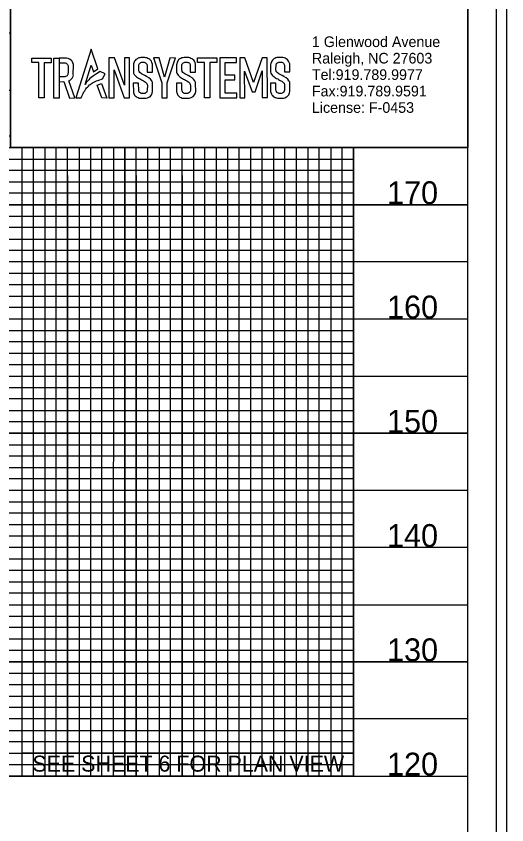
# Model space of a CAD drawing. Extents: x 1779926 to 1781610, y 620464 to 621564.
# Drawn here: x 1781395.5 to 1781610, y 621017.9 to 621371.7 of the extents above; entities that cross this region are included whole.
import ezdxf

# ---------------------------------------------------------------- set-up
doc = ezdxf.new("R2010")
doc.units = 0
for name, color, linetype in [('Exist Vertical Profile Vertical Axis Label', 7, 'Continuous'), ('Old_Level_2', 7, 'Continuous'), ('Old_Level_58', 7, 'Continuous'), ('Prop DSN Text', 7, 'Continuous'), ('Prop Grid Mask', 7, 'Continuous'), ('Scratch_Level_0', 7, 'Continuous'), ('Sheet DOT Grid CELL', 7, 'Continuous'), ('Sheet Layout Profile Border Port 1', 7, 'Continuous'), ('Sheet Plot Border Inside CELL', 7, 'Continuous'), ('Sheet Plot Border Outside CELL', 7, 'Continuous'), ('Sheet Profile CELL', 7, 'Continuous'), ('Sheet Profile Grid Major CELL', 7, 'Continuous'), ('Sheet Profile Grid Middle CELL', 7, 'Continuous'), ('Sheet Profile Grid Minor CELL', 7, 'Continuous')]:
    doc.layers.add(name, color=color, linetype=linetype)

msp = doc.modelspace()

# ---------------------------------------------------------------- linework, layer by layer
at = {"layer": 'Old_Level_58'}
msp.add_lwpolyline([(1781392.96, 621378.14), (1781592.95, 621378.14), (1781592.95, 621314.19), (1781392.96, 621314.19)], close=True, dxfattribs=at)
at = {"layer": 'Prop Grid Mask'}
msp.add_lwpolyline([(1781542.96, 621049.19), (1781397.96, 621049.19), (1781397.96, 621039.19), (1781542.96, 621039.19)], close=True, dxfattribs=at)
at = {"layer": 'Scratch_Level_0'}
msp.add_lwpolyline([(1780142.96, 621039.19), (1780142.96, 621539.19), (1781392.96, 621539.19), (1781392.96, 621314.19), (1781542.96, 621314.19), (1781542.96, 621039.19)], close=True, dxfattribs=at)
at = {"layer": 'Sheet DOT Grid CELL'}
for p, q in [((1781442.96, 621039.19), (1781442.96, 621314.19)), ((1781492.96, 621039.19), (1781492.96, 621314.19)), ((1781542.96, 621039.19), (1781542.96, 621314.19)), ((1781592.96, 621289.19), (1780092.96, 621289.19)), ((1781592.96, 621239.19), (1780092.96, 621239.19)), ((1781592.96, 621189.19), (1780092.96, 621189.19)), ((1781592.96, 621139.19), (1780092.96, 621139.19)), ((1781592.96, 621089.19), (1780092.96, 621089.19))]:
    msp.add_line(p, q, dxfattribs=at)
at = {"layer": 'Sheet Layout Profile Border Port 1'}
msp.add_lwpolyline([(1780142.96, 621378.14), (1780142.96, 621039.19), (1781542.96, 621039.19), (1781542.96, 621314.19)], dxfattribs=at)
for points in [[(1781428.25, 621357.23), (1781421.58, 621335.89), (1781423.81, 621335.9), (1781424.15, 621336.74), (1781424.72, 621337.9), (1781425.03, 621338.53), (1781425.41, 621339.07), (1781425.93, 621339.83), (1781426.26, 621340.3), (1781426.64, 621340.69), (1781427.02, 621341.08), (1781427.51, 621341.58), (1781427.92, 621341.85), (1781428.33, 621342.18), (1781428.89, 621342.5), (1781429.38, 621342.78), (1781430.6, 621343.35), (1781431.6, 621343.76), (1781433.24, 621344.32), (1781434.38, 621346.46), (1781432.2, 621347.42), (1781430.57, 621346.53), (1781429.19, 621345.63), (1781428.21, 621344.83), (1781427.69, 621344.41), (1781427.15, 621343.84), (1781426.62, 621343.27), (1781426.22, 621342.85), (1781425.84, 621342.2), (1781425.63, 621341.84), (1781428.26, 621350.22), (1781429.26, 621347.33), (1781431.16, 621348.58)], [(1781402.29, 621353.38), (1781410.75, 621353.39), (1781410.75, 621351.31), (1781407.64, 621351.31), (1781407.66, 621335.89), (1781405.31, 621335.89), (1781405.29, 621351.41), (1781402.32, 621351.41)], [(1781411.91, 621353.37), (1781414.22, 621353.38), (1781414.24, 621335.81), (1781411.92, 621335.81)], [(1781414.22, 621351.29), (1781416.61, 621351.29), (1781416.91, 621351.24), (1781417.32, 621351.08), (1781417.64, 621350.86), (1781417.87, 621350.59), (1781418.03, 621350.26), (1781418.15, 621350), (1781418.15, 621349.42), (1781418.16, 621346.93), (1781418.1, 621346.6), (1781418.01, 621346.16), (1781417.88, 621345.86), (1781417.68, 621345.6), (1781417.41, 621345.39), (1781416.99, 621345.24), (1781416.66, 621345.2), (1781416.34, 621345.15), (1781414.23, 621345.14), (1781414.24, 621343.03), (1781416.35, 621343.05), (1781418.72, 621335.88), (1781421.13, 621335.91), (1781418.48, 621343.45), (1781418.86, 621343.58), (1781419.4, 621343.98), (1781419.89, 621344.52), (1781420.23, 621345.15), (1781420.45, 621345.78), (1781420.43, 621345.97), (1781420.48, 621350.53), (1781420.27, 621351.28), (1781419.91, 621351.96), (1781419.5, 621352.43), (1781418.8, 621352.9), (1781418.12, 621353.13), (1781417.45, 621353.35), (1781417.04, 621353.35), (1781414.22, 621353.38)], [(1781436.02, 621353.41), (1781436.03, 621335.95), (1781438.27, 621335.95), (1781438.26, 621348.23), (1781442.71, 621335.93), (1781444.96, 621335.96), (1781444.94, 621353.46), (1781442.76, 621353.46), (1781442.78, 621341.48), (1781438.37, 621353.42)], [(1781452.72, 621347.24), (1781455.03, 621347.24), (1781455.02, 621350.72), (1781454.83, 621351.42), (1781454.55, 621352.01), (1781454.25, 621352.4), (1781453.88, 621352.76), (1781453.44, 621353.04), (1781453.01, 621353.21), (1781453.01, 621353.21), (1781452.55, 621353.41), (1781452.07, 621353.53), (1781451.75, 621353.61), (1781450, 621353.57), (1781449.47, 621353.48), (1781449.02, 621353.4), (1781448.55, 621353.16), (1781448.15, 621352.95), (1781447.76, 621352.67), (1781447.45, 621352.35), (1781447.2, 621351.99), (1781447.01, 621351.59), (1781446.75, 621350.9), (1781446.7, 621350.38), (1781446.7, 621347.21), (1781446.82, 621346.74), (1781447.05, 621346.24), (1781447.34, 621345.83), (1781447.63, 621345.52), (1781448.08, 621345.17), (1781448.54, 621344.83), (1781448.82, 621344.61), (1781449.3, 621344.38), (1781449.79, 621344.16), (1781450.18, 621343.9), (1781450.62, 621343.62), (1781451.15, 621343.35), (1781451.58, 621343.13), (1781452.01, 621342.82), (1781452.32, 621342.52), (1781452.57, 621342.28), (1781452.72, 621341.8), (1781452.82, 621341.5), (1781452.78, 621339.27), (1781452.62, 621338.78), (1781452.38, 621338.36), (1781452.05, 621338.07), (1781451.69, 621337.91), (1781451.35, 621337.84), (1781450.39, 621337.82), (1781450.07, 621337.91), (1781449.74, 621338.1), (1781449.41, 621338.3), (1781449.27, 621338.63), (1781449.13, 621338.97), (1781449.01, 621339.23), (1781448.98, 621342.35), (1781446.64, 621342.32), (1781446.68, 621338.61), (1781446.8, 621338.33), (1781447.07, 621337.46), (1781447.24, 621337.17), (1781447.5, 621336.85), (1781447.88, 621336.48), (1781448.18, 621336.29), (1781448.62, 621336.1), (1781448.78, 621336.04), (1781449.2, 621335.86), (1781449.74, 621335.8), (1781450.13, 621335.76), (1781452.27, 621335.82), (1781452.87, 621335.96), (1781453.69, 621336.33), (1781453.97, 621336.46), (1781454.6, 621337.25), (1781454.93, 621338.04), (1781455.08, 621338.75), (1781455.03, 621342.17), (1781455.02, 621342.64), (1781454.89, 621343.02), (1781454.7, 621343.37), (1781454.16, 621344.13), (1781453.45, 621344.69), (1781452.48, 621345.27), (1781451.73, 621345.71), (1781450.27, 621346.48), (1781449.52, 621347.04), (1781449.19, 621347.46), (1781449.11, 621347.74), (1781449.03, 621348.03), (1781449.08, 621350.46), (1781449.2, 621350.71), (1781449.33, 621350.97), (1781449.51, 621351.12), (1781449.74, 621351.32), (1781450, 621351.42), (1781450.25, 621351.53), (1781450.4, 621351.5), (1781450.42, 621351.58), (1781451.38, 621351.56), (1781451.65, 621351.45), (1781451.93, 621351.34), (1781452.21, 621351.23), (1781452.34, 621351.04), (1781452.52, 621350.76), (1781452.61, 621350.48), (1781452.71, 621350.21), (1781452.7, 621349.9)], [(1781457.99, 621353.42), (1781455.45, 621353.42), (1781459.07, 621342.54), (1781459.1, 621335.99), (1781461.49, 621336.01), (1781461.46, 621342.5), (1781465.12, 621353.46), (1781462.62, 621353.39), (1781460.31, 621345.05)], [(1781471.59, 621347.26), (1781473.9, 621347.26), (1781473.89, 621350.74), (1781473.7, 621351.44), (1781473.42, 621352.03), (1781473.12, 621352.42), (1781472.75, 621352.77), (1781472.31, 621353.06), (1781471.88, 621353.23), (1781471.88, 621353.23), (1781471.43, 621353.42), (1781470.94, 621353.55), (1781470.62, 621353.63), (1781468.87, 621353.59), (1781468.34, 621353.5), (1781467.89, 621353.42), (1781467.43, 621353.18), (1781467.02, 621352.97), (1781466.63, 621352.68), (1781466.32, 621352.37), (1781466.08, 621352.01), (1781465.88, 621351.61), (1781465.63, 621350.91), (1781465.58, 621350.4), (1781465.58, 621347.23), (1781465.69, 621346.75), (1781465.92, 621346.26), (1781466.21, 621345.85), (1781466.51, 621345.54), (1781466.96, 621345.19), (1781467.41, 621344.84), (1781467.69, 621344.62), (1781468.18, 621344.4), (1781468.66, 621344.17), (1781469.05, 621343.92), (1781469.49, 621343.63), (1781470.02, 621343.37), (1781470.45, 621343.15), (1781470.88, 621342.83), (1781471.19, 621342.54), (1781471.44, 621342.3), (1781471.59, 621341.82), (1781471.69, 621341.52), (1781471.65, 621339.28), (1781471.49, 621338.8), (1781471.25, 621338.38), (1781470.92, 621338.09), (1781470.56, 621337.93), (1781470.22, 621337.86), (1781469.26, 621337.84), (1781468.94, 621337.93), (1781468.61, 621338.12), (1781468.28, 621338.31), (1781468.14, 621338.65), (1781468, 621338.98), (1781467.88, 621339.25), (1781467.85, 621342.36), (1781465.51, 621342.34), (1781465.55, 621338.63), (1781465.67, 621338.34), (1781465.94, 621337.48), (1781466.12, 621337.19), (1781466.37, 621336.87), (1781466.75, 621336.5), (1781467.05, 621336.3), (1781467.49, 621336.12), (1781467.65, 621336.05), (1781468.08, 621335.87), (1781468.61, 621335.82), (1781469, 621335.78), (1781471.15, 621335.84), (1781471.74, 621335.98), (1781472.57, 621336.35), (1781472.85, 621336.48), (1781473.47, 621337.27), (1781473.8, 621338.05), (1781473.96, 621338.76), (1781473.9, 621342.19), (1781473.9, 621342.66), (1781473.76, 621343.03), (1781473.57, 621343.39), (1781473.03, 621344.15), (1781472.33, 621344.7), (1781471.35, 621345.28), (1781470.61, 621345.73), (1781469.14, 621346.49), (1781468.39, 621347.06), (1781468.06, 621347.48), (1781467.98, 621347.76), (1781467.91, 621348.05), (1781467.95, 621350.48), (1781468.08, 621350.73), (1781468.2, 621350.99), (1781468.38, 621351.14), (1781468.61, 621351.33), (1781468.87, 621351.44), (1781469.13, 621351.55), (1781469.27, 621351.52), (1781469.29, 621351.59), (1781470.25, 621351.58), (1781470.52, 621351.47), (1781470.8, 621351.36), (1781471.08, 621351.25), (1781471.21, 621351.06), (1781471.39, 621350.78), (1781471.49, 621350.5), (1781471.58, 621350.23), (1781471.57, 621349.92)], [(1781474.74, 621353.45), (1781483.21, 621353.45), (1781483.21, 621351.38), (1781480.1, 621351.38), (1781480.12, 621335.96), (1781477.77, 621335.95), (1781477.75, 621351.48), (1781474.78, 621351.48)], [(1781491.82, 621353.45), (1781484.43, 621353.45), (1781484.45, 621336.02), (1781491.92, 621336.03), (1781491.92, 621338), (1781486.87, 621337.99), (1781486.87, 621343.84), (1781491.08, 621343.84), (1781491.08, 621345.91), (1781486.83, 621345.91), (1781486.83, 621351.41), (1781491.84, 621351.41)], [(1781499.19, 621342.6), (1781495.38, 621353.53), (1781493.17, 621353.42), (1781493.25, 621335.96), (1781495.36, 621335.97), (1781495.31, 621347.65), (1781498.57, 621338.66), (1781499.92, 621338.63), (1781502.99, 621347.76), (1781503.03, 621336.04), (1781505.32, 621336.05), (1781505.25, 621353.47), (1781502.95, 621353.46)], [(1781512.72, 621347.3), (1781515.03, 621347.3), (1781515.03, 621350.77), (1781514.83, 621351.48), (1781514.55, 621352.07), (1781514.25, 621352.46), (1781513.88, 621352.81), (1781513.44, 621353.09), (1781513.02, 621353.27), (1781513.02, 621353.27), (1781512.56, 621353.46), (1781512.08, 621353.58), (1781511.76, 621353.66), (1781510.01, 621353.63), (1781509.48, 621353.54), (1781509.02, 621353.46), (1781508.56, 621353.22), (1781508.15, 621353.01), (1781507.76, 621352.72), (1781507.45, 621352.41), (1781507.21, 621352.04), (1781507.01, 621351.65), (1781506.76, 621350.95), (1781506.71, 621350.44), (1781506.71, 621347.27), (1781506.82, 621346.79), (1781507.05, 621346.3), (1781507.34, 621345.89), (1781507.64, 621345.58), (1781508.09, 621345.23), (1781508.54, 621344.88), (1781508.83, 621344.66), (1781509.31, 621344.44), (1781509.79, 621344.21), (1781510.18, 621343.96), (1781510.62, 621343.67), (1781511.15, 621343.41), (1781511.58, 621343.19), (1781512.01, 621342.87), (1781512.32, 621342.58), (1781512.57, 621342.34), (1781512.73, 621341.86), (1781512.82, 621341.56), (1781512.79, 621339.32), (1781512.62, 621338.84), (1781512.38, 621338.42), (1781512.05, 621338.13), (1781511.7, 621337.97), (1781511.36, 621337.9), (1781510.39, 621337.88), (1781510.07, 621337.97), (1781509.74, 621338.16), (1781509.41, 621338.35), (1781509.27, 621338.69), (1781509.13, 621339.02), (1781509.02, 621339.29), (1781508.98, 621342.4), (1781506.64, 621342.37), (1781506.69, 621338.66), (1781506.8, 621338.38), (1781507.07, 621337.52), (1781507.25, 621337.23), (1781507.5, 621336.91), (1781507.88, 621336.53), (1781508.19, 621336.34), (1781508.62, 621336.16), (1781508.78, 621336.09), (1781509.21, 621335.91), (1781509.74, 621335.86), (1781510.14, 621335.82), (1781512.28, 621335.87), (1781512.87, 621336.01), (1781513.7, 621336.39), (1781513.98, 621336.51), (1781514.6, 621337.31), (1781514.93, 621338.09), (1781515.09, 621338.8), (1781515.04, 621342.22), (1781515.03, 621342.7), (1781514.9, 621343.07), (1781514.71, 621343.43), (1781514.17, 621344.19), (1781513.46, 621344.74), (1781512.48, 621345.32), (1781511.74, 621345.77), (1781510.28, 621346.53), (1781509.52, 621347.09), (1781509.19, 621347.52), (1781509.12, 621347.8), (1781509.04, 621348.08), (1781509.08, 621350.51), (1781509.21, 621350.77), (1781509.33, 621351.02), (1781509.51, 621351.18), (1781509.74, 621351.37), (1781510, 621351.48), (1781510.26, 621351.59), (1781510.41, 621351.56), (1781510.42, 621351.63), (1781511.38, 621351.62), (1781511.66, 621351.51), (1781511.93, 621351.4), (1781512.21, 621351.29), (1781512.34, 621351.09), (1781512.53, 621350.82), (1781512.62, 621350.54), (1781512.71, 621350.26), (1781512.7, 621349.96)], [(1781430.86, 621341.52), (1781432.78, 621342.29), (1781435.04, 621335.85), (1781432.94, 621335.93)]]:
    msp.add_lwpolyline(points, close=True, dxfattribs=at)
at = {"layer": 'Sheet Plot Border Inside CELL'}
msp.add_lwpolyline([(1779938.96, 620486.64), (1781605.46, 620486.64), (1781605.46, 621541.74), (1779938.96, 621541.74)], close=True, dxfattribs=at)
at = {"layer": 'Sheet Plot Border Outside CELL'}
msp.add_lwpolyline([(1779925.96, 620464.19), (1781609.96, 620464.19), (1781609.96, 621564.19), (1779925.96, 621564.19)], close=True, dxfattribs=at)
at = {"layer": 'Sheet Profile CELL'}
msp.add_line((1780092.96, 621039.19), (1781592.96, 621039.19), dxfattribs=at)
msp.add_lwpolyline([(1781592.96, 621539.19), (1780092.96, 621539.19), (1780092.96, 620489.19), (1781592.96, 620489.19)], close=True, dxfattribs=at)
at = {"layer": 'Sheet Profile Grid Major CELL'}
for points in [[(1781542.96, 621314.19), (1781542.96, 621039.19), (1781592.96, 621039.19), (1781592.96, 621389.19)], [(1781392.91, 621339.19), (1780092.96, 621339.19), (1780092.96, 621289.19), (1781592.96, 621289.19)], [(1781442.96, 621314.19), (1781442.96, 621039.19), (1781492.96, 621039.19), (1781492.96, 621039.19), (1781492.96, 621314.19)], [(1781592.96, 621239.19), (1780092.96, 621239.19), (1780092.96, 621189.19), (1781592.96, 621189.19)], [(1781592.96, 621139.19), (1780092.96, 621139.19), (1780092.96, 621139.19), (1780092.96, 621089.19), (1781592.96, 621089.19)]]:
    msp.add_lwpolyline(points, dxfattribs=at)
at = {"layer": 'Sheet Profile Grid Middle CELL'}
for points in [[(1781167.96, 621039.19), (1781217.96, 621039.19), (1781217.96, 621539.19), (1781267.96, 621539.19), (1781267.96, 621039.19), (1781317.96, 621039.19), (1781317.96, 621539.19), (1781367.96, 621539.19), (1781367.96, 621039.19), (1781417.96, 621039.19), (1781417.96, 621314.19)], [(1781392.91, 621364.19), (1780092.96, 621364.19), (1780092.96, 621314.19), (1781417.96, 621314.19)], [(1781417.96, 621314.19), (1781592.96, 621314.19)], [(1781417.96, 621301.99), (1781417.96, 621039.19), (1781467.96, 621039.19), (1781467.96, 621314.19)], [(1781467.96, 621301.99), (1781467.96, 621039.19), (1781517.96, 621039.19), (1781517.96, 621314.19)], [(1781592.96, 621264.19), (1780092.96, 621264.19), (1780092.96, 621214.19), (1781592.96, 621214.19)], [(1781592.96, 621164.19), (1780092.96, 621164.19), (1780092.96, 621114.19), (1781592.96, 621114.19)], [(1781592.96, 621064.19), (1780092.96, 621064.19)]]:
    msp.add_lwpolyline(points, dxfattribs=at)
at = {"layer": 'Sheet Profile Grid Minor CELL'}
for p, q in [((1781542.96, 621304.19), (1780142.96, 621304.19)), ((1780142.96, 621299.19), (1781542.96, 621299.19)), ((1781542.96, 621294.19), (1780142.96, 621294.19)), ((1780142.96, 621284.19), (1781542.96, 621284.19)), ((1781542.96, 621279.19), (1780142.96, 621279.19)), ((1780142.96, 621274.19), (1781542.96, 621274.19)), ((1781542.96, 621269.19), (1780142.96, 621269.19)), ((1780142.96, 621259.19), (1781542.96, 621259.19)), ((1781542.96, 621254.19), (1780142.96, 621254.19)), ((1780142.96, 621249.19), (1781542.96, 621249.19)), ((1781542.96, 621244.19), (1780142.96, 621244.19)), ((1780142.96, 621234.19), (1781542.96, 621234.19)), ((1781542.96, 621229.19), (1780142.96, 621229.19)), ((1780142.96, 621224.19), (1781542.96, 621224.19)), ((1781542.96, 621219.19), (1780142.96, 621219.19)), ((1780142.96, 621209.19), (1781542.96, 621209.19)), ((1781542.96, 621204.19), (1780142.96, 621204.19)), ((1780142.96, 621199.19), (1781542.96, 621199.19)), ((1781542.96, 621194.19), (1780142.96, 621194.19)), ((1780142.96, 621184.19), (1781542.96, 621184.19)), ((1781542.96, 621179.19), (1780142.96, 621179.19)), ((1780142.96, 621174.19), (1781542.96, 621174.19)), ((1781542.96, 621169.19), (1780142.96, 621169.19)), ((1780142.96, 621159.19), (1781542.96, 621159.19)), ((1781542.96, 621154.19), (1780142.96, 621154.19)), ((1781542.96, 621149.19), (1780142.96, 621149.19)), ((1781542.96, 621144.19), (1780142.96, 621144.19)), ((1780142.96, 621134.19), (1781542.96, 621134.19)), ((1781542.96, 621129.19), (1780142.96, 621129.19)), ((1780142.96, 621124.19), (1781542.96, 621124.19)), ((1781542.96, 621119.19), (1780142.96, 621119.19)), ((1780142.96, 621109.19), (1781542.96, 621109.19)), ((1781542.96, 621104.19), (1780142.96, 621104.19)), ((1780142.96, 621099.19), (1781542.96, 621099.19)), ((1781542.96, 621094.19), (1780142.96, 621094.19)), ((1780142.96, 621084.19), (1781542.96, 621084.19)), ((1781542.96, 621079.19), (1780142.96, 621079.19)), ((1780142.96, 621074.19), (1781542.96, 621074.19)), ((1781542.96, 621069.19), (1780142.96, 621069.19)), ((1780142.96, 621059.19), (1781542.96, 621059.19)), ((1781542.96, 621054.19), (1780142.96, 621054.19)), ((1780142.96, 621049.19), (1781542.96, 621049.19))]:
    msp.add_line(p, q, dxfattribs=at)
for points in [[(1781392.91, 621319.19), (1780142.96, 621319.19), (1780142.96, 621309.19), (1781542.96, 621309.19)], [(1781397.96, 621314.19), (1781397.96, 621039.19), (1781402.96, 621039.19), (1781402.96, 621314.19)], [(1781407.96, 621314.19), (1781407.96, 621039.19), (1781412.96, 621039.19), (1781412.96, 621314.19)], [(1781422.96, 621314.19), (1781422.96, 621039.19), (1781422.96, 621039.19), (1781427.96, 621039.19), (1781432.96, 621039.19), (1781432.96, 621314.19)], [(1781427.96, 621314.19), (1781427.96, 621039.19)], [(1781437.94, 621314.19), (1781437.86, 621039.24), (1781442.86, 621039.24), (1781447.96, 621039.19), (1781447.96, 621314.19)], [(1781447.96, 621301.99), (1781447.96, 621039.19), (1781452.96, 621039.19), (1781452.96, 621314.19)], [(1781457.96, 621314.19), (1781457.96, 621039.19), (1781462.96, 621039.19), (1781462.96, 621314.19)], [(1781472.96, 621314.19), (1781472.96, 621039.19), (1781477.96, 621039.19), (1781477.96, 621314.19)], [(1781482.96, 621314.19), (1781482.96, 621039.19), (1781487.96, 621039.19), (1781487.96, 621314.19)], [(1781497.96, 621314.19), (1781497.96, 621039.19), (1781502.96, 621039.19), (1781502.96, 621314.19)], [(1781507.96, 621314.19), (1781507.96, 621039.19), (1781512.96, 621039.19), (1781512.96, 621314.19)], [(1781522.96, 621314.19), (1781522.96, 621039.19), (1781527.96, 621039.19), (1781527.96, 621314.19)], [(1781532.96, 621314.19), (1781532.96, 621039.19), (1781537.96, 621039.19), (1781537.96, 621314.19)], [(1781542.96, 621044.19), (1780142.96, 621044.19)]]:
    msp.add_lwpolyline(points, dxfattribs=at)

# ---------------------------------------------------------------- texts
at = {"layer": 'Exist Vertical Profile Vertical Axis Label'}
for s, p in [('170', (1781557.59, 621289.44)), ('160', (1781557.59, 621239.44)), ('150', (1781557.59, 621189.44)), ('140', (1781557.59, 621139.44)), ('130', (1781557.59, 621089.44)), ('120', (1781557.59, 621039.44))]:
    msp.add_text(s, height=10, dxfattribs=at).set_placement(p)
at = {"layer": 'Old_Level_2'}
for s, p in [('1 Glenwood Avenue', (1781524.75, 621358.18)), ('Raleigh, NC 27603', (1781524.75, 621350.98)), ('Tel:919.789.9977 ', (1781524.75, 621343.79)), ('Fax:919.789.9591', (1781524.75, 621336.59)), ('License: F-0453', (1781524.75, 621329.39))]:
    msp.add_text(s, height=4.6576, rotation=360, dxfattribs=at).set_placement(p)
at = {"layer": 'Prop DSN Text'}
msp.add_text('SEE SHEET 6 FOR PLAN VIEW', height=7, dxfattribs=at).set_placement((1781402.54, 621041.14))

doc.saveas('drawing.dxf')
